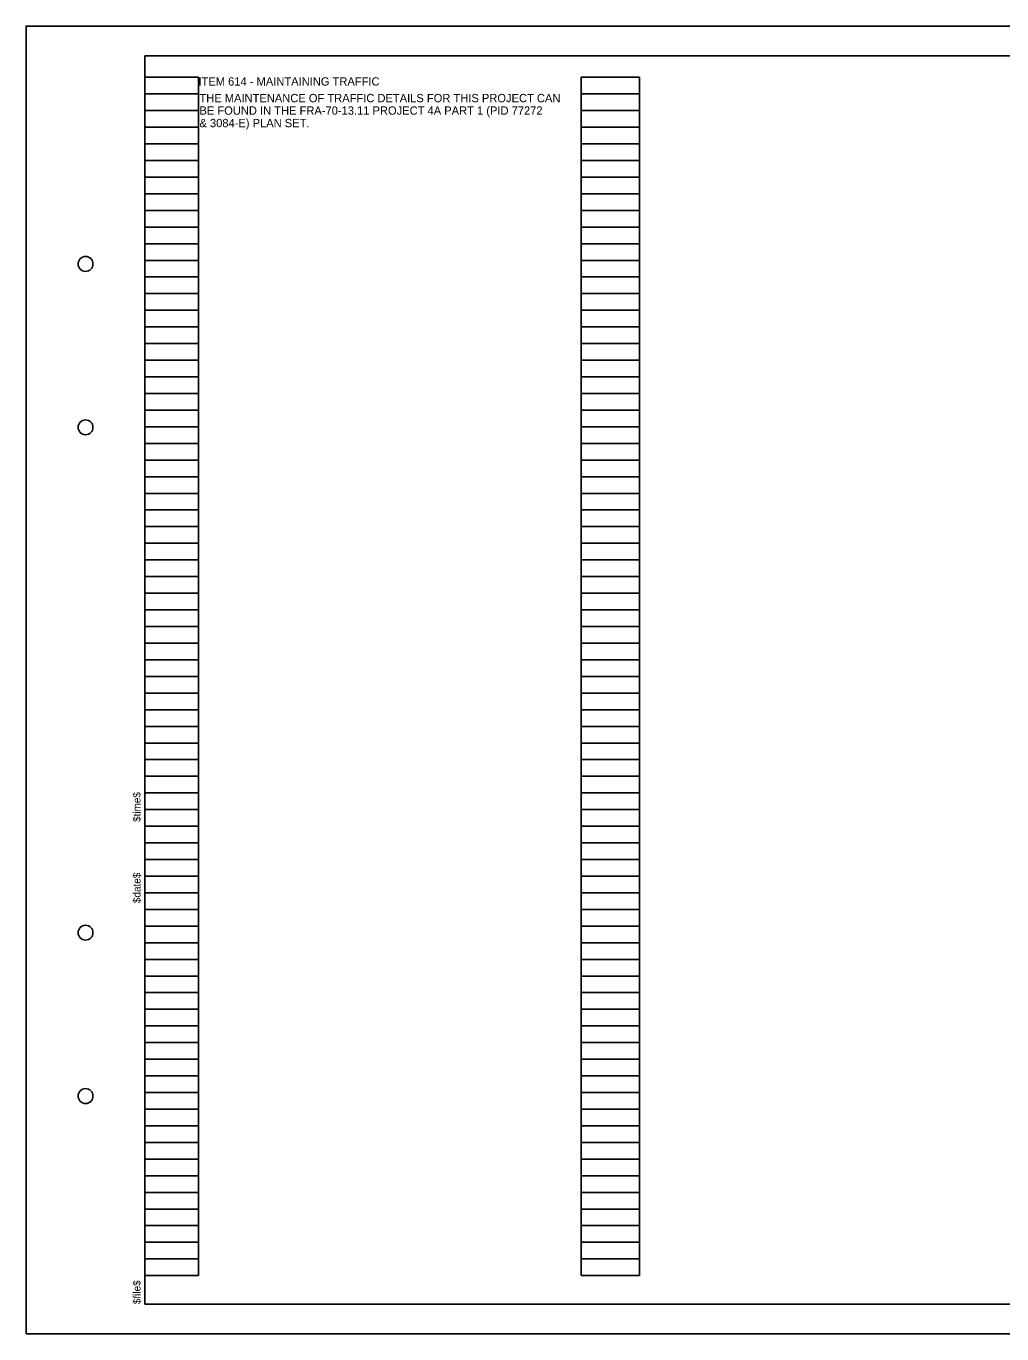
# Model space of a CAD drawing. Extents: x 1835969 to 1838545, y 714903 to 716193.
# Drawn here: x 1836002.8 to 1836019.22, y 714961.41 to 714983.41 of the extents above; entities that cross this region are included whole.
import ezdxf

# ---------------------------------------------------------------- set-up
doc = ezdxf.new("R2010")
doc.units = 0
for name, color, linetype in [('Default', 7, 'Continuous'), ('SC_Scratch2', 7, 'Continuous'), ('SH_Border', 7, 'Continuous'), ('SH_Cut_Line', 7, 'Continuous'), ('SH_Data', 7, 'Continuous'), ('TX_P_Misc', 7, 'Continuous')]:
    doc.layers.add(name, color=color, linetype=linetype)

msp = doc.modelspace()

# ---------------------------------------------------------------- linework, layer by layer
at = {"layer": 'SC_Scratch2'}
for p, q in [((1836004.801, 714962.39), (1836004.801, 714982.55)), ((1836004.801, 714982.55), (1836005.701, 714982.55)), ((1836005.701, 714962.39), (1836005.701, 714982.55)), ((1836012.141, 714962.39), (1836012.141, 714982.55)), ((1836012.141, 714982.55), (1836013.121, 714982.55)), ((1836013.121, 714962.39), (1836013.121, 714982.55)), ((1836004.801, 714982.27), (1836005.701, 714982.27)), ((1836012.141, 714982.27), (1836013.121, 714982.27)), ((1836004.801, 714981.99), (1836005.701, 714981.99)), ((1836012.141, 714981.99), (1836013.121, 714981.99)), ((1836004.801, 714981.71), (1836005.701, 714981.71)), ((1836012.141, 714981.71), (1836013.121, 714981.71)), ((1836004.801, 714981.43), (1836005.701, 714981.43)), ((1836012.141, 714981.43), (1836013.121, 714981.43)), ((1836004.801, 714981.15), (1836005.701, 714981.15)), ((1836012.141, 714981.15), (1836013.121, 714981.15)), ((1836004.801, 714980.87), (1836005.701, 714980.87)), ((1836012.141, 714980.87), (1836013.121, 714980.87)), ((1836004.801, 714980.59), (1836005.701, 714980.59)), ((1836012.141, 714980.59), (1836013.121, 714980.59)), ((1836004.801, 714980.31), (1836005.701, 714980.31)), ((1836012.141, 714980.31), (1836013.121, 714980.31)), ((1836004.801, 714980.03), (1836005.701, 714980.03)), ((1836012.141, 714980.03), (1836013.121, 714980.03)), ((1836004.801, 714979.75), (1836005.701, 714979.75)), ((1836012.141, 714979.75), (1836013.121, 714979.75)), ((1836004.801, 714979.47), (1836005.701, 714979.47)), ((1836012.141, 714979.47), (1836013.121, 714979.47)), ((1836004.801, 714979.19), (1836005.701, 714979.19)), ((1836012.141, 714979.19), (1836013.121, 714979.19)), ((1836004.801, 714978.91), (1836005.701, 714978.91)), ((1836012.141, 714978.91), (1836013.121, 714978.91)), ((1836004.801, 714978.63), (1836005.701, 714978.63)), ((1836012.141, 714978.63), (1836013.121, 714978.63)), ((1836004.801, 714978.35), (1836005.701, 714978.35)), ((1836012.141, 714978.35), (1836013.121, 714978.35)), ((1836004.801, 714978.07), (1836005.701, 714978.07)), ((1836012.141, 714978.07), (1836013.121, 714978.07)), ((1836004.801, 714977.79), (1836005.701, 714977.79)), ((1836012.141, 714977.79), (1836013.121, 714977.79)), ((1836004.801, 714977.51), (1836005.701, 714977.51)), ((1836012.141, 714977.51), (1836013.121, 714977.51)), ((1836004.801, 714977.23), (1836005.701, 714977.23)), ((1836012.141, 714977.23), (1836013.121, 714977.23)), ((1836004.801, 714976.95), (1836005.701, 714976.95)), ((1836012.141, 714976.95), (1836013.121, 714976.95)), ((1836004.801, 714976.67), (1836005.701, 714976.67)), ((1836012.141, 714976.67), (1836013.121, 714976.67)), ((1836004.801, 714976.39), (1836005.701, 714976.39)), ((1836012.141, 714976.39), (1836013.121, 714976.39)), ((1836004.801, 714976.11), (1836005.701, 714976.11)), ((1836012.141, 714976.11), (1836013.121, 714976.11)), ((1836004.801, 714975.83), (1836005.701, 714975.83)), ((1836012.141, 714975.83), (1836013.121, 714975.83)), ((1836004.801, 714975.55), (1836005.701, 714975.55)), ((1836012.141, 714975.55), (1836013.121, 714975.55)), ((1836004.801, 714975.27), (1836005.701, 714975.27)), ((1836012.141, 714975.27), (1836013.121, 714975.27)), ((1836004.801, 714974.99), (1836005.701, 714974.99)), ((1836012.141, 714974.99), (1836013.121, 714974.99)), ((1836004.801, 714974.71), (1836005.701, 714974.71)), ((1836012.141, 714974.71), (1836013.121, 714974.71)), ((1836004.801, 714974.43), (1836005.701, 714974.43)), ((1836012.141, 714974.43), (1836013.121, 714974.43)), ((1836004.801, 714974.15), (1836005.701, 714974.15)), ((1836012.141, 714974.15), (1836013.121, 714974.15)), ((1836004.801, 714973.87), (1836005.701, 714973.87)), ((1836012.141, 714973.87), (1836013.121, 714973.87)), ((1836004.801, 714973.59), (1836005.701, 714973.59)), ((1836012.141, 714973.59), (1836013.121, 714973.59)), ((1836004.801, 714973.31), (1836005.701, 714973.31)), ((1836012.141, 714973.31), (1836013.121, 714973.31)), ((1836004.801, 714973.03), (1836005.701, 714973.03)), ((1836012.141, 714973.03), (1836013.121, 714973.03)), ((1836004.801, 714972.75), (1836005.701, 714972.75)), ((1836012.141, 714972.75), (1836013.121, 714972.75)), ((1836004.801, 714972.47), (1836005.701, 714972.47)), ((1836012.141, 714972.47), (1836013.121, 714972.47)), ((1836004.801, 714972.19), (1836005.701, 714972.19)), ((1836012.141, 714972.19), (1836013.121, 714972.19)), ((1836004.801, 714971.91), (1836005.701, 714971.91)), ((1836012.141, 714971.91), (1836013.121, 714971.91)), ((1836004.801, 714971.63), (1836005.701, 714971.63)), ((1836012.141, 714971.63), (1836013.121, 714971.63)), ((1836004.801, 714971.35), (1836005.701, 714971.35)), ((1836012.141, 714971.35), (1836013.121, 714971.35)), ((1836004.801, 714971.07), (1836005.701, 714971.07)), ((1836012.141, 714971.07), (1836013.121, 714971.07)), ((1836004.801, 714970.79), (1836005.701, 714970.79)), ((1836012.141, 714970.79), (1836013.121, 714970.79)), ((1836004.801, 714970.51), (1836005.701, 714970.51)), ((1836012.141, 714970.51), (1836013.121, 714970.51)), ((1836004.801, 714970.23), (1836005.701, 714970.23)), ((1836012.141, 714970.23), (1836013.121, 714970.23)), ((1836004.801, 714969.95), (1836005.701, 714969.95)), ((1836012.141, 714969.95), (1836013.121, 714969.95)), ((1836004.801, 714969.67), (1836005.701, 714969.67)), ((1836012.141, 714969.67), (1836013.121, 714969.67)), ((1836004.801, 714969.39), (1836005.701, 714969.39)), ((1836012.141, 714969.39), (1836013.121, 714969.39)), ((1836004.801, 714969.11), (1836005.701, 714969.11)), ((1836012.141, 714969.11), (1836013.121, 714969.11)), ((1836004.801, 714968.83), (1836005.701, 714968.83)), ((1836012.141, 714968.83), (1836013.121, 714968.83)), ((1836004.801, 714968.55), (1836005.701, 714968.55)), ((1836012.141, 714968.55), (1836013.121, 714968.55)), ((1836004.801, 714968.27), (1836005.701, 714968.27)), ((1836012.141, 714968.27), (1836013.121, 714968.27)), ((1836004.801, 714967.99), (1836005.701, 714967.99)), ((1836012.141, 714967.99), (1836013.121, 714967.99)), ((1836004.801, 714967.71), (1836005.701, 714967.71)), ((1836012.141, 714967.71), (1836013.121, 714967.71)), ((1836004.801, 714967.43), (1836005.701, 714967.43)), ((1836012.141, 714967.43), (1836013.121, 714967.43)), ((1836004.801, 714967.15), (1836005.701, 714967.15)), ((1836012.141, 714967.15), (1836013.121, 714967.15)), ((1836004.801, 714966.87), (1836005.701, 714966.87)), ((1836012.141, 714966.87), (1836013.121, 714966.87)), ((1836004.801, 714966.59), (1836005.701, 714966.59)), ((1836012.141, 714966.59), (1836013.121, 714966.59)), ((1836004.801, 714966.31), (1836005.701, 714966.31)), ((1836012.141, 714966.31), (1836013.121, 714966.31)), ((1836004.801, 714966.03), (1836005.701, 714966.03)), ((1836012.141, 714966.03), (1836013.121, 714966.03)), ((1836004.801, 714965.75), (1836005.701, 714965.75)), ((1836012.141, 714965.75), (1836013.121, 714965.75)), ((1836004.801, 714965.47), (1836005.701, 714965.47)), ((1836012.141, 714965.47), (1836013.121, 714965.47)), ((1836004.801, 714965.19), (1836005.701, 714965.19)), ((1836012.141, 714965.19), (1836013.121, 714965.19)), ((1836004.801, 714964.91), (1836005.701, 714964.91)), ((1836012.141, 714964.91), (1836013.121, 714964.91)), ((1836004.801, 714964.63), (1836005.701, 714964.63)), ((1836012.141, 714964.63), (1836013.121, 714964.63)), ((1836004.801, 714964.35), (1836005.701, 714964.35)), ((1836012.141, 714964.35), (1836013.121, 714964.35)), ((1836004.801, 714964.07), (1836005.701, 714964.07)), ((1836012.141, 714964.07), (1836013.121, 714964.07)), ((1836004.801, 714963.79), (1836005.701, 714963.79)), ((1836012.141, 714963.79), (1836013.121, 714963.79)), ((1836004.801, 714963.51), (1836005.701, 714963.51)), ((1836012.141, 714963.51), (1836013.121, 714963.51)), ((1836004.801, 714963.23), (1836005.701, 714963.23)), ((1836012.141, 714963.23), (1836013.121, 714963.23)), ((1836004.801, 714962.95), (1836005.701, 714962.95)), ((1836012.141, 714962.95), (1836013.121, 714962.95)), ((1836004.801, 714962.67), (1836005.701, 714962.67)), ((1836012.141, 714962.67), (1836013.121, 714962.67)), ((1836004.801, 714962.39), (1836005.701, 714962.39)), ((1836012.141, 714962.39), (1836013.121, 714962.39)), ((1836002.801, 714961.41), (1836002.801, 714961.41))]:
    msp.add_line(p, q, dxfattribs=at)
at = {"layer": 'SH_Border'}
msp.add_lwpolyline([(1836004.801, 714982.91), (1836036.301, 714982.91), (1836036.301, 714961.91), (1836004.801, 714961.91)], close=True, dxfattribs=at)
for centre in [(1836003.801, 714979.41), (1836003.801, 714976.66), (1836003.801, 714968.16), (1836003.801, 714965.41)]:
    msp.add_circle(centre, 0.125, dxfattribs=at)
at = {"layer": 'SH_Cut_Line'}
msp.add_lwpolyline([(1836002.801, 714961.41), (1836036.801, 714961.41), (1836036.801, 714983.41), (1836002.801, 714983.41)], close=True, dxfattribs=at)
at = {"layer": 'SH_Data'}
for p, q in [((1836004.801, 714962.39), (1836004.801, 714982.55)), ((1836004.801, 714982.55), (1836005.701, 714982.55)), ((1836005.701, 714962.39), (1836005.701, 714982.55)), ((1836012.141, 714962.39), (1836012.141, 714982.55)), ((1836012.141, 714982.55), (1836013.121, 714982.55)), ((1836013.121, 714962.39), (1836013.121, 714982.55)), ((1836004.801, 714982.27), (1836005.701, 714982.27)), ((1836012.141, 714982.27), (1836013.121, 714982.27)), ((1836004.801, 714981.99), (1836005.701, 714981.99)), ((1836012.141, 714981.99), (1836013.121, 714981.99)), ((1836004.801, 714981.71), (1836005.701, 714981.71)), ((1836012.141, 714981.71), (1836013.121, 714981.71)), ((1836004.801, 714981.43), (1836005.701, 714981.43)), ((1836012.141, 714981.43), (1836013.121, 714981.43)), ((1836004.801, 714981.15), (1836005.701, 714981.15)), ((1836012.141, 714981.15), (1836013.121, 714981.15)), ((1836004.801, 714980.87), (1836005.701, 714980.87)), ((1836012.141, 714980.87), (1836013.121, 714980.87)), ((1836004.801, 714980.59), (1836005.701, 714980.59)), ((1836012.141, 714980.59), (1836013.121, 714980.59)), ((1836004.801, 714980.31), (1836005.701, 714980.31)), ((1836012.141, 714980.31), (1836013.121, 714980.31)), ((1836004.801, 714980.03), (1836005.701, 714980.03)), ((1836012.141, 714980.03), (1836013.121, 714980.03)), ((1836004.801, 714979.75), (1836005.701, 714979.75)), ((1836012.141, 714979.75), (1836013.121, 714979.75)), ((1836004.801, 714979.47), (1836005.701, 714979.47)), ((1836012.141, 714979.47), (1836013.121, 714979.47)), ((1836004.801, 714979.19), (1836005.701, 714979.19)), ((1836012.141, 714979.19), (1836013.121, 714979.19)), ((1836004.801, 714978.91), (1836005.701, 714978.91)), ((1836012.141, 714978.91), (1836013.121, 714978.91)), ((1836004.801, 714978.63), (1836005.701, 714978.63)), ((1836012.141, 714978.63), (1836013.121, 714978.63)), ((1836004.801, 714978.35), (1836005.701, 714978.35)), ((1836012.141, 714978.35), (1836013.121, 714978.35)), ((1836004.801, 714978.07), (1836005.701, 714978.07)), ((1836012.141, 714978.07), (1836013.121, 714978.07)), ((1836004.801, 714977.79), (1836005.701, 714977.79)), ((1836012.141, 714977.79), (1836013.121, 714977.79)), ((1836004.801, 714977.51), (1836005.701, 714977.51)), ((1836012.141, 714977.51), (1836013.121, 714977.51)), ((1836004.801, 714977.23), (1836005.701, 714977.23)), ((1836012.141, 714977.23), (1836013.121, 714977.23)), ((1836004.801, 714976.95), (1836005.701, 714976.95)), ((1836012.141, 714976.95), (1836013.121, 714976.95)), ((1836004.801, 714976.67), (1836005.701, 714976.67)), ((1836012.141, 714976.67), (1836013.121, 714976.67)), ((1836004.801, 714976.39), (1836005.701, 714976.39)), ((1836012.141, 714976.39), (1836013.121, 714976.39)), ((1836004.801, 714976.11), (1836005.701, 714976.11)), ((1836012.141, 714976.11), (1836013.121, 714976.11)), ((1836004.801, 714975.83), (1836005.701, 714975.83)), ((1836012.141, 714975.83), (1836013.121, 714975.83)), ((1836004.801, 714975.55), (1836005.701, 714975.55)), ((1836012.141, 714975.55), (1836013.121, 714975.55)), ((1836004.801, 714975.27), (1836005.701, 714975.27)), ((1836012.141, 714975.27), (1836013.121, 714975.27)), ((1836004.801, 714974.99), (1836005.701, 714974.99)), ((1836012.141, 714974.99), (1836013.121, 714974.99)), ((1836004.801, 714974.71), (1836005.701, 714974.71)), ((1836012.141, 714974.71), (1836013.121, 714974.71)), ((1836004.801, 714974.43), (1836005.701, 714974.43)), ((1836012.141, 714974.43), (1836013.121, 714974.43)), ((1836004.801, 714974.15), (1836005.701, 714974.15)), ((1836012.141, 714974.15), (1836013.121, 714974.15)), ((1836004.801, 714973.87), (1836005.701, 714973.87)), ((1836012.141, 714973.87), (1836013.121, 714973.87)), ((1836004.801, 714973.59), (1836005.701, 714973.59)), ((1836012.141, 714973.59), (1836013.121, 714973.59)), ((1836004.801, 714973.31), (1836005.701, 714973.31)), ((1836012.141, 714973.31), (1836013.121, 714973.31)), ((1836004.801, 714973.03), (1836005.701, 714973.03)), ((1836012.141, 714973.03), (1836013.121, 714973.03)), ((1836004.801, 714972.75), (1836005.701, 714972.75)), ((1836012.141, 714972.75), (1836013.121, 714972.75)), ((1836004.801, 714972.47), (1836005.701, 714972.47)), ((1836012.141, 714972.47), (1836013.121, 714972.47)), ((1836004.801, 714972.19), (1836005.701, 714972.19)), ((1836012.141, 714972.19), (1836013.121, 714972.19)), ((1836004.801, 714971.91), (1836005.701, 714971.91)), ((1836012.141, 714971.91), (1836013.121, 714971.91)), ((1836004.801, 714971.63), (1836005.701, 714971.63)), ((1836012.141, 714971.63), (1836013.121, 714971.63)), ((1836004.801, 714971.35), (1836005.701, 714971.35)), ((1836012.141, 714971.35), (1836013.121, 714971.35)), ((1836004.801, 714971.07), (1836005.701, 714971.07)), ((1836012.141, 714971.07), (1836013.121, 714971.07)), ((1836004.801, 714970.79), (1836005.701, 714970.79)), ((1836012.141, 714970.79), (1836013.121, 714970.79)), ((1836004.801, 714970.51), (1836005.701, 714970.51)), ((1836012.141, 714970.51), (1836013.121, 714970.51)), ((1836004.801, 714970.23), (1836005.701, 714970.23)), ((1836012.141, 714970.23), (1836013.121, 714970.23)), ((1836004.801, 714969.95), (1836005.701, 714969.95)), ((1836012.141, 714969.95), (1836013.121, 714969.95)), ((1836004.801, 714969.67), (1836005.701, 714969.67)), ((1836012.141, 714969.67), (1836013.121, 714969.67)), ((1836004.801, 714969.39), (1836005.701, 714969.39)), ((1836012.141, 714969.39), (1836013.121, 714969.39)), ((1836004.801, 714969.11), (1836005.701, 714969.11)), ((1836012.141, 714969.11), (1836013.121, 714969.11)), ((1836004.801, 714968.83), (1836005.701, 714968.83)), ((1836012.141, 714968.83), (1836013.121, 714968.83)), ((1836004.801, 714968.55), (1836005.701, 714968.55)), ((1836012.141, 714968.55), (1836013.121, 714968.55)), ((1836004.801, 714968.27), (1836005.701, 714968.27)), ((1836012.141, 714968.27), (1836013.121, 714968.27)), ((1836004.801, 714967.99), (1836005.701, 714967.99)), ((1836012.141, 714967.99), (1836013.121, 714967.99)), ((1836004.801, 714967.71), (1836005.701, 714967.71)), ((1836012.141, 714967.71), (1836013.121, 714967.71)), ((1836004.801, 714967.43), (1836005.701, 714967.43)), ((1836012.141, 714967.43), (1836013.121, 714967.43)), ((1836004.801, 714967.15), (1836005.701, 714967.15)), ((1836012.141, 714967.15), (1836013.121, 714967.15)), ((1836004.801, 714966.87), (1836005.701, 714966.87)), ((1836012.141, 714966.87), (1836013.121, 714966.87)), ((1836004.801, 714966.59), (1836005.701, 714966.59)), ((1836012.141, 714966.59), (1836013.121, 714966.59)), ((1836004.801, 714966.31), (1836005.701, 714966.31)), ((1836012.141, 714966.31), (1836013.121, 714966.31)), ((1836004.801, 714966.03), (1836005.701, 714966.03)), ((1836012.141, 714966.03), (1836013.121, 714966.03)), ((1836004.801, 714965.75), (1836005.701, 714965.75)), ((1836012.141, 714965.75), (1836013.121, 714965.75)), ((1836004.801, 714965.47), (1836005.701, 714965.47)), ((1836012.141, 714965.47), (1836013.121, 714965.47)), ((1836004.801, 714965.19), (1836005.701, 714965.19)), ((1836012.141, 714965.19), (1836013.121, 714965.19)), ((1836004.801, 714964.91), (1836005.701, 714964.91)), ((1836012.141, 714964.91), (1836013.121, 714964.91)), ((1836004.801, 714964.63), (1836005.701, 714964.63)), ((1836012.141, 714964.63), (1836013.121, 714964.63)), ((1836004.801, 714964.35), (1836005.701, 714964.35)), ((1836012.141, 714964.35), (1836013.121, 714964.35)), ((1836004.801, 714964.07), (1836005.701, 714964.07)), ((1836012.141, 714964.07), (1836013.121, 714964.07)), ((1836004.801, 714963.79), (1836005.701, 714963.79)), ((1836012.141, 714963.79), (1836013.121, 714963.79)), ((1836004.801, 714963.51), (1836005.701, 714963.51)), ((1836012.141, 714963.51), (1836013.121, 714963.51)), ((1836004.801, 714963.23), (1836005.701, 714963.23)), ((1836012.141, 714963.23), (1836013.121, 714963.23)), ((1836004.801, 714962.95), (1836005.701, 714962.95)), ((1836012.141, 714962.95), (1836013.121, 714962.95)), ((1836004.801, 714962.67), (1836005.701, 714962.67)), ((1836012.141, 714962.67), (1836013.121, 714962.67)), ((1836004.801, 714962.39), (1836005.701, 714962.39)), ((1836012.141, 714962.39), (1836013.121, 714962.39)), ((1836002.801, 714961.41), (1836002.801, 714961.41))]:
    msp.add_line(p, q, dxfattribs=at)

# ---------------------------------------------------------------- texts
at = {"layer": 'Default'}
for s, p in [('$time$', (1836004.726, 714970.022)), ('$date$', (1836004.726, 714968.657)), ('$file$', (1836004.726, 714961.91))]:
    msp.add_text(s, height=0.125, rotation=90, dxfattribs=at).set_placement(p)
at = {"layer": 'TX_P_Misc'}
for s, p in [('ITEM 614 - MAINTAINING TRAFFIC', (1836005.701, 714982.41)), ('THE MAINTENANCE OF TRAFFIC DETAILS FOR THIS PROJECT CAN ', (1836005.718, 714982.13)), ('BE FOUND IN THE FRA-70-13.11 PROJECT 4A PART 1 (PID 77272 ', (1836005.718, 714981.92)), ('& 3084-E) PLAN SET. ', (1836005.718, 714981.71))]:
    msp.add_text(s, height=0.14, rotation=0, dxfattribs=at).set_placement(p)

doc.saveas('drawing.dxf')
